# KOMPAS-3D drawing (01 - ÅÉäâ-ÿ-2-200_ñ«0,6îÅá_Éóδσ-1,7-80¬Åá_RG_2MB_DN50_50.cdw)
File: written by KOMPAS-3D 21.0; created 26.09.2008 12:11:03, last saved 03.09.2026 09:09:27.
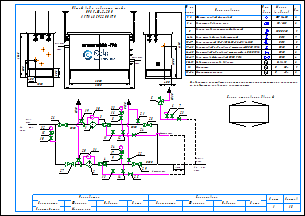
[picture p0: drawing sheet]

Sheets 1-2: A3, landscape

Document properties: Наименование: Макро:21; Автор: RaskoAdmin; Форматы листов документа: 2xA3; Полное имя файла: \\UR38nt01\Departments\КТО\КБ ПУРДГ\Заявки\Прайс-лист на типовые шкафы ГРПШ\ПРДГ_стандарт_20_03_2026\ПРДГ с RG_2MB\ПРДГ-Ш-2-200_до0,6МПа_Рвых-1,7-80кПа_RG_2MB_DN50_50.cdw

Title block, sheet 1: Наименование: Пункт учета газа / ПУГ-Ш-400-Р / ЛГТИ.485922.001ТУ; designation: ЛГТИ.03.4411141; sheet number: 1; Количество листов документа: 2; organisation: ООО "ЭЛЬСТЕР Газэлектроника"; Форматы листов документа: A3; stored path: C:\Рабочие документы\Компас\ПУГ\Схема.cdw; Разработал: Устинов; Проверил: Кошкин; Утвердил: Кошкин
Title block, sheet 2: sheet number: 2; stored path: D:\Рабочие документы\Заявки\ПУРДГ\ПУРДГ-ШУЭО-2-100-Р 4411220.cdw; designation, second copy: ЛГТИ.03.4411141-

Views: Вид 1, Вид 2
Referenced files: wcvoit.frw
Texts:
  Normal
  Вход
  газа
  PDI
  Выход
  Р=     кПа
  DN50
  DN20
  Импульс DN20
  ≥5DN
  HYSWLongFangSong
  № на
  схеме
  Усл.
  обозн.
  Марка
  (модель)
  Кол.
  Фильтр газовый фланцевый
  ФГ 16-50
  Регулятор давления газа
  RG/2MB
  Клапан предохранительный сбросной
  КПС DN20
  Кран шаровой газовый латунный
  DN15
  Кран кнопочный VE-РАСКО-НЗ-1,6-G1/2-М20
  Кран шаровой "под приварку" штуцерный DN20 PN16
  Кран шаровой "под приварку" штуцерный п/п DN20 PN16
  Кран шаровой фланцевый DN50 PN16
  Индикатор перепада давления
  Delta 15
  Манометр
  Манометр-напоромер
  0...     МПа
  0...     кПа
  Общий вид и габариты шкафа
  ПРДГ-Ш-2-200
  Выход газа
  Вход газа
  Схема открывания дверей
  Р=       МПа
  logo-rasko-ge.png
  Предприятие изготовитель может заменять комплектующие на аналогичные,
  не ухудшающие заявленных характеристик.
  Должность
  Конструктор
  Фамилия
  Подпись
  Дата
  Согласовано
  Максимкин
  Лист
  Листов
  POLYLINE_STYLE_0.18_RGB_0_0_0
  POLYLINE_STYLE_0.50_RGB_0_0_0
  POLYLINE_STYLE_0.34_RGB_0_0_0
  PHANTOM_RGB_0_0_0_SC_1_THICK_0.18
  K5LT_THIN_RGB_0_0_0_THICK_0.18
  K5LT32769_RGB_0_0_0_THICK_0.18
  K5LT12_RGB_0_0_0_SC_1_THICK_0.18
  K5LT_DASHED_RGB_0_0_0_SC_1_THICK_0.18
  ACISOTGL_RGB_0_0_0_SC_0.8_THICK_0.25
  CONTINUOUS_RGB_0_127_31_THICK_0.3
  CONTINUOUS_RGB_0_0_255_THICK_0.35
  CONTINUOUS_RGB_255_0_0_THICK_0.35
  POLYLINE_STYLE_0.25_RGB_0_0_0
  CONTINUOUS_RGB_0_0_0_THICK_0.5
  POLYLINE_STYLE_0.35_RGB_0_0_255
  CONTINUOUS_RGB_0_0_0_THICK_0.4
  CONTINUOUS_RGB_0_0_0_THICK_0.35
  Без оформления
Dimensions and other numbers on the sheet: 1; 2; 3; 4; 5; 10; 27; 28; 29; 23; 8; 12; 19; 20; 21; 22; 25; 24; 30; 31; 15; 16; 26; 6; 7; 11; 14; 13; 33; 1, 2; 3, 4; 6-14; 9; 15-17; 19-23; 24-25; 26-29; 30-31; 32; 33-34; 1000; 400; 1050; 500; 305; 2000; 4130; 1565; 2300; 17; 34; 18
